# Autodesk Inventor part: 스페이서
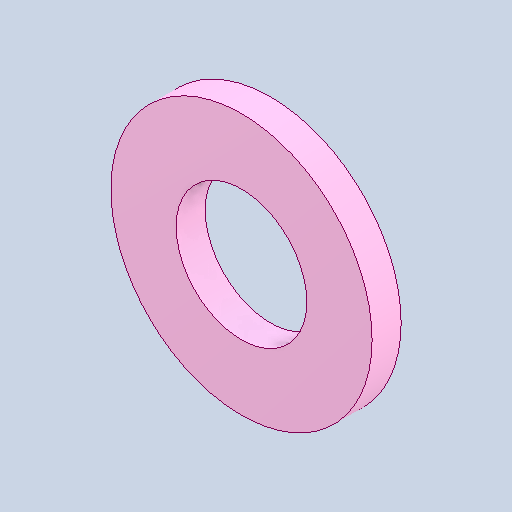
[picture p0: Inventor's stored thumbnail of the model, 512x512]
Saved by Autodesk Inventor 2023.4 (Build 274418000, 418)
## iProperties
Created: 2024-04
Part Number: 스페이서
Material: 강철, 연강
Document SubType Name: Modeling
Designer: EDU
Density: 7.86 g/cm^3
Appearance: 기본값
Author: jhkim
Sending System: Autodesk Inventor 2025
Preprocessor: ST-DEVELOPER v20
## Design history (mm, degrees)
node "스페이서1"
node "솔리드2"
node "솔리드1"
